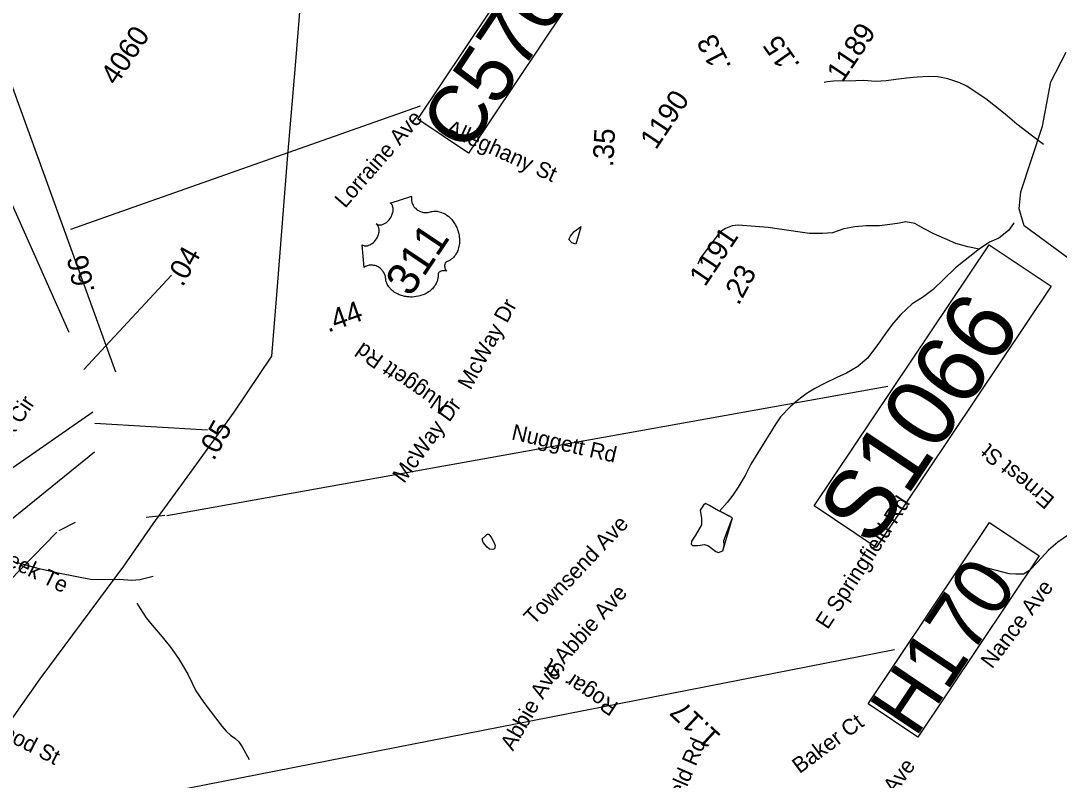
# Model space of a CAD drawing. Extents: x 1716282 to 1717158, y 799307 to 801078.
# Drawn here: x 1716680.6 to 1716771.4, y 799417.7 to 799484.2 of the extents above; entities that cross this region are included whole.
import ezdxf

# ---------------------------------------------------------------- set-up
doc = ezdxf.new("R2010")
doc.units = 0
for name, color, linetype in [('Exist Hydrographic Misc Water Feature', 7, 'Continuous'), ('Exist Road Non-System Structure Non-Sys NCDOT Number Label', 7, 'Continuous'), ('Exist Road Non-System Type 51 Label', 7, 'Continuous'), ('Exist Road Primary Interstate Mileage Hundredths English Label', 7, 'Continuous'), ('Exist Road Primary Interstate Structure Culvert Number Label', 7, 'Continuous'), ('Exist Road Primary Interstate Structure Ovrhead Sign CELL', 7, 'Continuous'), ('Exist Road Primary US Mileage Hundredths English Label', 7, 'Continuous'), ('Exist Road Primary US Shield CELL', 7, 'Continuous'), ('Exist Road Primary US Shield Number Label', 7, 'Continuous'), ('Exist Road Primary US Structure Standard Bridge Number Label', 7, 'Continuous'), ('Exist Road Secondary Mileage Hundredths English Label', 7, 'Continuous'), ('Exist Road Secondary Mileage Tenths English Label', 7, 'Continuous'), ('Exist Road Secondary Type 51 Number Label', 7, 'Continuous'), ('Exist Utilities Electrical Transmission Line', 7, 'Continuous')]:
    doc.layers.add(name, color=color, linetype=linetype)

msp = doc.modelspace()

# ---------------------------------------------------------------- linework, layer by layer
at = {"layer": 'Exist Hydrographic Misc Water Feature'}
for points in [[(1716773.614, 799462.354), (1716768.362, 799466.219), (1716767.899, 799467.716), (1716768.07, 799469.206), (1716769.939, 799474.952), (1716770.68, 799478.835), (1716772.026, 799481.424)], [(1716770.044, 799473.355), (1716768.975, 799474.155), (1716767.706, 799475.128), (1716766.687, 799476), (1716764.996, 799477.33), (1716764.326, 799477.789), (1716763.327, 799478.436), (1716762.727, 799478.74), (1716761.66, 799479.082), (1716760.793, 799479.252), (1716760.014, 799479.294), (1716758.984, 799479.225), (1716758.056, 799479.154), (1716757.122, 799479.02), (1716756.267, 799478.901), (1716755.335, 799478.871), (1716754.322, 799478.932), (1716753.613, 799478.924), (1716751.681, 799478.873), (1716751.151, 799478.815), (1716750.844, 799478.777)], [(1716764.405, 799464.175), (1716763.425, 799464.387), (1716762.367, 799464.687), (1716761.391, 799465.11), (1716760.454, 799465.538), (1716759.598, 799465.982), (1716758.783, 799466.435), (1716758.003, 799466.58), (1716757.278, 799466.442), (1716755.69, 799466.228), (1716754.524, 799466.216), (1716753.533, 799466.155), (1716752.59, 799465.957), (1716751.588, 799465.623), (1716750.702, 799465.559), (1716749.576, 799465.556), (1716746.957, 799465.939), (1716745.969, 799466.088), (1716743.325, 799466.279), (1716742.809, 799466.244), (1716742.227, 799466.01), (1716741.725, 799465.686), (1716740.009, 799463.38), (1716739.811, 799462.883)], [(1716767.472, 799466.504), (1716767.424, 799466.433), (1716766.974, 799465.827), (1716766.122, 799465.145), (1716765.33, 799464.806), (1716764.405, 799464.175)], [(1716729.129, 799464.629), (1716728.777, 799464.73), (1716728.53, 799465.038), (1716728.663, 799465.334), (1716729.005, 799465.733), (1716729.387, 799466.034), (1716729.59, 799466.177), (1716729.514, 799465.911), (1716729.129, 799464.629)], [(1716764.405, 799464.175), (1716764.292, 799464.111), (1716762.351, 799462.556), (1716761.342, 799461.593), (1716760.391, 799460.665), (1716759.458, 799459.965), (1716758.541, 799459.396), (1716757.566, 799458.482), (1716756.929, 799457.758), (1716756.359, 799457.025), (1716755.558, 799455.851), (1716754.635, 799454.653), (1716753.789, 799453.931), (1716752.817, 799453.33), (1716751.968, 799452.962), (1716750.9, 799452.427), (1716750.042, 799451.994), (1716749.297, 799451.519), (1716748.526, 799450.957), (1716747.934, 799450.45), (1716747.046, 799449.509), (1716746.636, 799448.91), (1716746.251, 799448.295)], [(1716746.251, 799448.295), (1716745.817, 799447.609), (1716744.44, 799445.387), (1716743.939, 799444.395), (1716743.34, 799443.365), (1716742.865, 799442.669), (1716742.384, 799442.016), (1716741.707, 799441.283)], [(1716781.419, 799444.301), (1716781.008, 799443.944), (1716780.12, 799443.569), (1716777.845, 799442.451), (1716774.721, 799440.757), (1716773.328, 799439.952), (1716771.292, 799438.567), (1716770.465, 799437.869), (1716769.55, 799436.84), (1716768.818, 799436.076), (1716768.293, 799435.77), (1716767.624, 799435.768), (1716767.037, 799435.784), (1716764.599, 799436.43), (1716764.221, 799436.547)], [(1716741.707, 799441.283), (1716741.411, 799441.415), (1716740.843, 799441.766), (1716740.475, 799441.948), (1716740.297, 799441.79), (1716740.026, 799441.342), (1716740.139, 799440.633), (1716740.116, 799440.085), (1716739.6, 799439.175), (1716739.263, 799438.631), (1716739.228, 799438.375), (1716739.331, 799438.269), (1716739.814, 799438.255), (1716740.403, 799438.346), (1716740.755, 799438.244), (1716741.369, 799437.754), (1716741.617, 799437.655), (1716741.988, 799437.787), (1716742.107, 799438.269), (1716742.089, 799438.704), (1716742.412, 799439.538), (1716742.71, 799440.386), (1716742.843, 799440.684), (1716742.011, 799441.11), (1716741.707, 799441.283)], [(1716741.707, 799441.283), (1716740.843, 799441.766), (1716740.475, 799441.948), (1716740.297, 799441.79), (1716740.026, 799441.342), (1716740.139, 799440.633), (1716740.116, 799440.085), (1716739.6, 799439.175), (1716739.263, 799438.631), (1716739.228, 799438.375), (1716739.331, 799438.269), (1716739.814, 799438.255), (1716740.403, 799438.346), (1716740.755, 799438.244), (1716741.369, 799437.754), (1716741.617, 799437.655), (1716741.988, 799437.787), (1716742.843, 799440.684), (1716741.707, 799441.283)], [(1716721.425, 799439.259), (1716721.53, 799439.259), (1716721.759, 799438.926), (1716721.987, 799438.487), (1716722.089, 799438.278), (1716722.022, 799437.974), (1716721.867, 799437.902), (1716721.587, 799437.954), (1716721.388, 799438.125), (1716721.039, 799438.54), (1716720.937, 799438.854), (1716721.207, 799439.094), (1716721.368, 799439.227), (1716721.425, 799439.259)], [(1716721.425, 799439.259), (1716721.53, 799439.259), (1716721.759, 799438.926), (1716721.987, 799438.487), (1716722.089, 799438.278), (1716722.022, 799437.974), (1716721.867, 799437.902), (1716721.587, 799437.954), (1716721.388, 799438.125), (1716721.039, 799438.54), (1716720.937, 799438.854), (1716721.207, 799439.094), (1716721.368, 799439.227), (1716721.425, 799439.259)], [(1716692.169, 799435.567), (1716691.015, 799435.266), (1716690.298, 799435.193), (1716689.237, 799435.286), (1716686.84, 799435.273), (1716684.022, 799435.828), (1716682.215, 799436.217), (1716680.628, 799436.671), (1716678.821, 799437.061), (1716676.606, 799437.52), (1716675.619, 799437.773), (1716674.739, 799438.129), (1716674.251, 799438.392), (1716673.722, 799438.544), (1716672.86, 799438.568), (1716672.216, 799438.551), (1716671.365, 799438.642)], [(1716690.751, 799433.234), (1716691.027, 799432.763), (1716691.556, 799431.945), (1716692.096, 799431.294), (1716692.955, 799430.288), (1716693.692, 799429.362), (1716694.381, 799428.365), (1716694.918, 799427.505), (1716695.234, 799426.94), (1716695.58, 799426.211), (1716695.893, 799425.539), (1716696.606, 799424.525), (1716698.184, 799422.464), (1716698.557, 799422.034), (1716698.939, 799421.668), (1716699.324, 799421.406), (1716699.674, 799421.097), (1716699.966, 799420.651), (1716700.573, 799419.532)]]:
    msp.add_lwpolyline(points, dxfattribs=at)
at = {"layer": 'Exist Road Non-System Structure Non-Sys NCDOT Number Label'}
msp.add_line((1716690.867, 799416.185), (1716756.996, 799429.156), dxfattribs=at)
msp.add_lwpolyline([(1716754.695, 799424.408), (1716765.317, 799440.279), (1716769.669, 799437.366), (1716759.046, 799421.495)], close=True, dxfattribs=at)
at = {"layer": 'Exist Road Primary Interstate Mileage Hundredths English Label'}
for p, q in [((1716686.106, 799453.665), (1716693.764, 799461.924)), ((1716687.062, 799448.978), (1716696.937, 799448.379))]:
    msp.add_line(p, q, dxfattribs=at)
at = {"layer": 'Exist Road Primary Interstate Structure Culvert Number Label'}
msp.add_line((1716684.965, 799465.926), (1716715.565, 799476.735), dxfattribs=at)
msp.add_lwpolyline([(1716715.319, 799475.573), (1716725.786, 799491.212), (1716730.228, 799488.239), (1716719.761, 799472.6)], close=True, dxfattribs=at)
at = {"layer": 'Exist Road Primary Interstate Structure Ovrhead Sign CELL'}
for p, q in [((1716693.38, 799440.89), (1716756.435, 799452.211)), ((1716683.945, 799439.587), (1716685.378, 799440.309)), ((1716691.55, 799440.752), (1716693.191, 799440.921)), ((1716683.741, 799439.418), (1716655.978, 799410.97))]:
    msp.add_line(p, q, dxfattribs=at)
msp.add_lwpolyline([(1716749.997, 799441.721), (1716765.289, 799464.568), (1716770.699, 799460.947), (1716755.407, 799438.1)], close=True, dxfattribs=at)
at = {"layer": 'Exist Road Primary US Shield CELL'}
msp.add_lwpolyline([(1716710.458, 799464.559), (1716710.513, 799464.526), (1716710.584, 799464.497), (1716710.623, 799464.485), (1716710.705, 799464.473), (1716710.811, 799464.473), (1716710.928, 799464.492), (1716711.042, 799464.526), (1716711.11, 799464.556), (1716711.215, 799464.612), (1716711.323, 799464.683), (1716711.429, 799464.772), (1716711.527, 799464.869), (1716711.623, 799464.984), (1716711.707, 799465.104), (1716711.785, 799465.242), (1716711.854, 799465.406), (1716711.882, 799465.485), (1716711.906, 799465.577), (1716711.924, 799465.666), (1716711.935, 799465.77), (1716711.936, 799465.857), (1716711.933, 799465.929), (1716711.914, 799466.04), (1716711.883, 799466.139), (1716711.86, 799466.187), (1716711.837, 799466.231), (1716711.778, 799466.31), (1716711.749, 799466.34), (1716711.682, 799466.393), (1716711.744, 799466.358), (1716711.785, 799466.339), (1716711.828, 799466.324), (1716711.877, 799466.314), (1716711.949, 799466.304), (1716712.015, 799466.304), (1716712.121, 799466.316), (1716712.178, 799466.33), (1716712.226, 799466.344), (1716712.344, 799466.391), (1716712.464, 799466.459), (1716712.519, 799466.494), (1716712.572, 799466.533), (1716712.635, 799466.585), (1716712.696, 799466.642), (1716712.752, 799466.701), (1716712.807, 799466.762), (1716712.859, 799466.828), (1716712.898, 799466.884), (1716712.944, 799466.954), (1716712.983, 799467.021), (1716713.02, 799467.092), (1716713.056, 799467.172), (1716713.083, 799467.239), (1716713.114, 799467.33), (1716713.135, 799467.416), (1716713.15, 799467.495), (1716713.161, 799467.603), (1716713.164, 799467.694), (1716713.158, 799467.766), (1716713.144, 799467.856), (1716713.118, 799467.95), (1716713.094, 799468.011), (1716713.063, 799468.064), (1716713.028, 799468.117), (1716712.985, 799468.164), (1716712.944, 799468.2), (1716712.907, 799468.227), (1716714.784, 799468.824), (1716714.776, 799468.786), (1716714.763, 799468.694), (1716714.759, 799468.617), (1716714.762, 799468.487), (1716714.77, 799468.427), (1716714.781, 799468.365), (1716714.795, 799468.305), (1716714.81, 799468.251), (1716714.837, 799468.179), (1716714.866, 799468.111), (1716714.901, 799468.041), (1716714.934, 799467.984), (1716715.011, 799467.876), (1716715.063, 799467.814), (1716715.111, 799467.764), (1716715.215, 799467.673), (1716715.267, 799467.633), (1716715.32, 799467.597), (1716715.379, 799467.562), (1716715.437, 799467.531), (1716715.5, 799467.502), (1716715.556, 799467.478), (1716715.628, 799467.453), (1716715.715, 799467.428), (1716715.802, 799467.41), (1716715.953, 799467.394), (1716716.117, 799467.393), (1716716.216, 799467.404), (1716716.306, 799467.421), (1716716.426, 799467.455), (1716716.492, 799467.473), (1716716.574, 799467.489), (1716716.721, 799467.507), (1716716.786, 799467.51), (1716716.858, 799467.51), (1716716.929, 799467.506), (1716717.003, 799467.5), (1716717.067, 799467.492), (1716717.207, 799467.464), (1716717.336, 799467.425), (1716717.402, 799467.403), (1716717.544, 799467.343), (1716717.612, 799467.31), (1716717.741, 799467.238), (1716717.889, 799467.139), (1716718.023, 799467.034), (1716718.169, 799466.897), (1716718.253, 799466.81), (1716718.344, 799466.699), (1716718.422, 799466.601), (1716718.529, 799466.444), (1716718.6, 799466.321), (1716718.679, 799466.171), (1716718.723, 799466.075), (1716718.767, 799465.967), (1716718.815, 799465.838), (1716718.86, 799465.694), (1716718.901, 799465.53), (1716718.926, 799465.402), (1716718.948, 799465.243), (1716718.958, 799465.149), (1716718.965, 799465.019), (1716718.965, 799464.848), (1716718.954, 799464.687), (1716718.939, 799464.554), (1716718.918, 799464.441), (1716718.885, 799464.298), (1716718.811, 799464.074), (1716718.779, 799463.996), (1716718.737, 799463.906), (1716718.693, 799463.825), (1716718.648, 799463.748), (1716718.581, 799463.648), (1716718.507, 799463.554), (1716718.431, 799463.469), (1716718.345, 799463.385), (1716718.246, 799463.303), (1716718.148, 799463.235), (1716718.039, 799463.172), (1716717.833, 799463.08), (1716717.778, 799463.051), (1716717.754, 799463.03), (1716717.71, 799462.971), (1716717.684, 799462.905), (1716717.668, 799462.83), (1716717.663, 799462.782), (1716717.662, 799462.714), (1716717.667, 799462.658), (1716717.679, 799462.587), (1716717.694, 799462.533), (1716717.706, 799462.492), (1716717.746, 799462.4), (1716717.769, 799462.362), (1716717.801, 799462.316), (1716717.854, 799462.259), (1716717.761, 799462.293), (1716717.692, 799462.305), (1716717.628, 799462.308), (1716717.569, 799462.306), (1716717.488, 799462.296), (1716717.423, 799462.282), (1716717.351, 799462.26), (1716717.285, 799462.229), (1716717.237, 799462.202), (1716717.197, 799462.174), (1716717.155, 799462.136), (1716717.126, 799462.1), (1716717.106, 799462.068), (1716717.088, 799462.019), (1716717.091, 799461.933), (1716717.092, 799461.853), (1716717.089, 799461.768), (1716717.079, 799461.672), (1716717.068, 799461.604), (1716717.051, 799461.525), (1716717.027, 799461.437), (1716716.994, 799461.344), (1716716.956, 799461.253), (1716716.92, 799461.174), (1716716.876, 799461.093), (1716716.832, 799461.023), (1716716.783, 799460.951), (1716716.733, 799460.888), (1716716.674, 799460.814), (1716716.594, 799460.727), (1716716.523, 799460.659), (1716716.443, 799460.59), (1716716.358, 799460.521), (1716716.26, 799460.452), (1716716.131, 799460.369), (1716716.035, 799460.316), (1716715.877, 799460.237), (1716715.673, 799460.157), (1716715.505, 799460.105), (1716715.375, 799460.072), (1716715.169, 799460.034), (1716715.041, 799460.016), (1716714.82, 799460.001), (1716714.667, 799460), (1716714.559, 799460.005), (1716714.389, 799460.02), (1716714.286, 799460.035), (1716714.14, 799460.062), (1716714.011, 799460.094), (1716713.891, 799460.128), (1716713.817, 799460.153), (1716713.691, 799460.202), (1716713.603, 799460.239), (1716713.487, 799460.296), (1716713.369, 799460.364), (1716713.264, 799460.432), (1716713.18, 799460.492), (1716713.086, 799460.569), (1716712.99, 799460.658), (1716712.912, 799460.74), (1716712.859, 799460.802), (1716712.797, 799460.883), (1716712.732, 799460.978), (1716712.676, 799461.077), (1716712.633, 799461.165), (1716712.591, 799461.266), (1716712.56, 799461.359), (1716712.533, 799461.472), (1716712.513, 799461.584), (1716712.504, 799461.68), (1716712.481, 799461.803), (1716712.463, 799461.871), (1716712.433, 799461.958), (1716712.401, 799462.033), (1716712.37, 799462.097), (1716712.321, 799462.186), (1716712.281, 799462.247), (1716712.214, 799462.334), (1716712.164, 799462.389), (1716712.096, 799462.457), (1716712.029, 799462.516), (1716711.94, 799462.581), (1716711.863, 799462.629), (1716711.768, 799462.679), (1716711.672, 799462.719), (1716711.584, 799462.748), (1716711.478, 799462.773), (1716711.397, 799462.786), (1716711.28, 799462.793), (1716711.166, 799462.79), (1716711.064, 799462.777), (1716710.97, 799462.758), (1716710.891, 799462.732), (1716710.819, 799462.705), (1716710.736, 799462.666), (1716710.663, 799462.624), (1716710.621, 799462.595)], close=True, dxfattribs=at)
at = {"layer": 'Exist Road Primary US Structure Standard Bridge Number Label'}
for p, q in [((1716684.825, 799456.904), (1716642.845, 799550.908)), ((1716688.898, 799453.424), (1716660.168, 799532.74)), ((1716686.891, 799449.917), (1716638.887, 799416.575)), ((1716687.045, 799446.435), (1716641.591, 799409.591))]:
    msp.add_line(p, q, dxfattribs=at)
at = {"layer": 'Exist Utilities Electrical Transmission Line'}
msp.add_lwpolyline([(1716679.055, 799422.002), (1716682.293, 799426.601), (1716685.151, 799430.438), (1716689.612, 799436.446), (1716692.165, 799440.148), (1716695.376, 799444.55), (1716699.265, 799449.937), (1716702.556, 799454.818), (1716703.041, 799460.925), (1716703.933, 799472.076), (1716704.64, 799480.604), (1716705.428, 799490.376)], dxfattribs=at)

# ---------------------------------------------------------------- texts
at = {"layer": 'Exist Road Non-System Structure Non-Sys NCDOT Number Label'}
msp.add_text('H170', height=5.075, rotation=56.20506, dxfattribs=at).set_placement((1716758.843, 799421.35))
at = {"layer": 'Exist Road Non-System Type 51 Label'}
for s, rotation, p in [('Lorraine Ave', 48.91699, (1716708.955, 799467.706)), ('Alleghany St', 335.53821, (1716717.667, 799474.308)), ('McWay Dr', 61.46756, (1716719.931, 799451.8)), ('Nuggett Rd', 145.14475, (1716718.14, 799450.777)), ('Mossbrook Cir', 56.20506, (1716675.294, 799440.917)), ('McWay Dr', 53.60524, (1716714.108, 799443.634)), ('Nuggett Rd', 347.23861, (1716723.443, 799447.562)), ('Ernest St', 140.24151, (1716771.108, 799442.405)), ('E Springfield Rd', 56.94781, (1716751.163, 799430.853)), ('Hidden Creek Te', 333.64208, (1716671.835, 799440.255)), ('Townsend Ave', 46.51082, (1716725.45, 799431.236)), ('Abbie Ave', 48.06984, (1716728.113, 799427.814)), ('Nance Ave', 52.90841, (1716765.537, 799427.412)), ('Rogar St', 146.20506, (1716732.95, 799424.409)), ('Abbie Ave', 59.91985, (1716723.638, 799420.221)), ('Brentwood St', 332.62893, (1716673.746, 799424.121)), ('Baker Ct', 36.7544, (1716748.709, 799418.257)), ('E Springfield Rd', 66.8835, (1716735.324, 799408.81)), ('Nance Ave', 53.11362, (1716753.497, 799411.772))]:
    msp.add_text(s, height=1.3775, rotation=rotation, dxfattribs=at).set_placement(p)
at = {"layer": 'Exist Road Primary Interstate Mileage Hundredths English Label'}
for s, rotation, p in [('.04', 60.78596, (1716694.744, 799460.816)), ('.66', 101.9544, (1716687.071, 799460.511)), ('.05', 60.60325, (1716697.468, 799445.608))]:
    msp.add_text(s, height=1.8125, rotation=rotation, dxfattribs=at).set_placement(p)
at = {"layer": 'Exist Road Primary Interstate Structure Culvert Number Label'}
msp.add_text('C576', height=5.075, rotation=56.20506, dxfattribs=at).set_placement((1716719.558, 799472.455))
at = {"layer": 'Exist Road Primary Interstate Structure Ovrhead Sign CELL'}
msp.add_text('S1066', height=6.09, rotation=56.20506, dxfattribs=at).set_placement((1716755.084, 799437.98))
at = {"layer": 'Exist Road Primary US Mileage Hundredths English Label'}
msp.add_text('.44', height=1.8125, rotation=19.68883, dxfattribs=at).set_placement((1716707.467, 799456.881))
at = {"layer": 'Exist Road Primary US Shield Number Label'}
msp.add_text('311', height=2.8275, rotation=56.20506, dxfattribs=at).set_placement((1716714.666, 799459.93))
at = {"layer": 'Exist Road Secondary Mileage Hundredths English Label'}
for s, rotation, p in [('.13', 117.03744, (1716742.781, 799480.169)), ('1.17', 136.93805, (1716741.922, 799421.631))]:
    msp.add_text(s, height=1.8125, rotation=rotation, dxfattribs=at).set_placement(p)
at = {"layer": 'Exist Road Secondary Mileage Tenths English Label'}
for s, rotation, p in [('.15', 125.1529, (1716748.81, 799480.323)), ('.35', 87.10766, (1716732.408, 799471.346)), ('.23', 61.45168, (1716743.378, 799459.203))]:
    msp.add_text(s, height=1.8125, rotation=rotation, dxfattribs=at).set_placement(p)
at = {"layer": 'Exist Road Secondary Type 51 Number Label'}
for s, p in [('1189', (1716752.456, 799478.691)), ('4060', (1716688.947, 799478.43)), ('1190', (1716736.14, 799472.812)), ('1191', (1716740.432, 799460.837))]:
    msp.add_text(s, height=1.8125, rotation=56.20506, dxfattribs=at).set_placement(p)

doc.saveas('drawing.dxf')
